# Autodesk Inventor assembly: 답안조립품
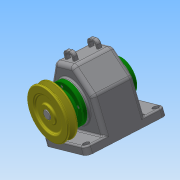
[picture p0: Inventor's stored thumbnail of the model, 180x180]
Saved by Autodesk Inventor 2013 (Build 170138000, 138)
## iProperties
Created: 2016-12
Part Number: 답안조립품
Document SubType Name: Assembly
Designer: Administrator
Author: Administrator
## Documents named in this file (15)
- C:\Users\Administrator\Desktop\461208V1017\답안조립품.iam
- C:\Users\Administrator\Desktop\461208V1017\V-벨트풀리.ipt
- C:\Users\Administrator\Desktop\461208V1017\뒤커버.ipt
- C:\Users\Administrator\Desktop\461208V1017\멈춤나사 - M4x10.ipt
- C:\Users\Administrator\Desktop\461208V1017\베어링 6203.ipt
- C:\Users\Administrator\Desktop\461208V1017\본체.ipt
- C:\Users\Administrator\Desktop\461208V1017\볼트 M3 x 8.ipt
- C:\Users\Administrator\Desktop\461208V1017\볼트 M3 x 10.ipt
- C:\Users\Administrator\Desktop\461208V1017\부시.ipt
- C:\Users\Administrator\Desktop\461208V1017\스퍼기어.ipt
- C:\Users\Administrator\Desktop\461208V1017\앞커버.ipt
- C:\Users\Administrator\Desktop\461208V1017\오일씰 28 40 8.ipt
- C:\Users\Administrator\Desktop\461208V1017\축.ipt
- C:\Users\Administrator\Desktop\461208V1017\키 - 5 x 5 x 18.ipt
- C:\Users\Administrator\Desktop\461208V1017\키 - 6 x 6 x 22.ipt
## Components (9 placed, 3 different names)
1. V-벨트풀리:1
2. ISO 4762 M3 x 10:1
3. ISO 4762 M3 x 10:2
4. ISO 4762 M3 x 10:3
5. ISO 4762 M3 x 10:4
6. ISO 4762 M3 x 8:1
7. ISO 4762 M3 x 8:2
8. ISO 4762 M3 x 8:3
9. ISO 4762 M3 x 8:4
